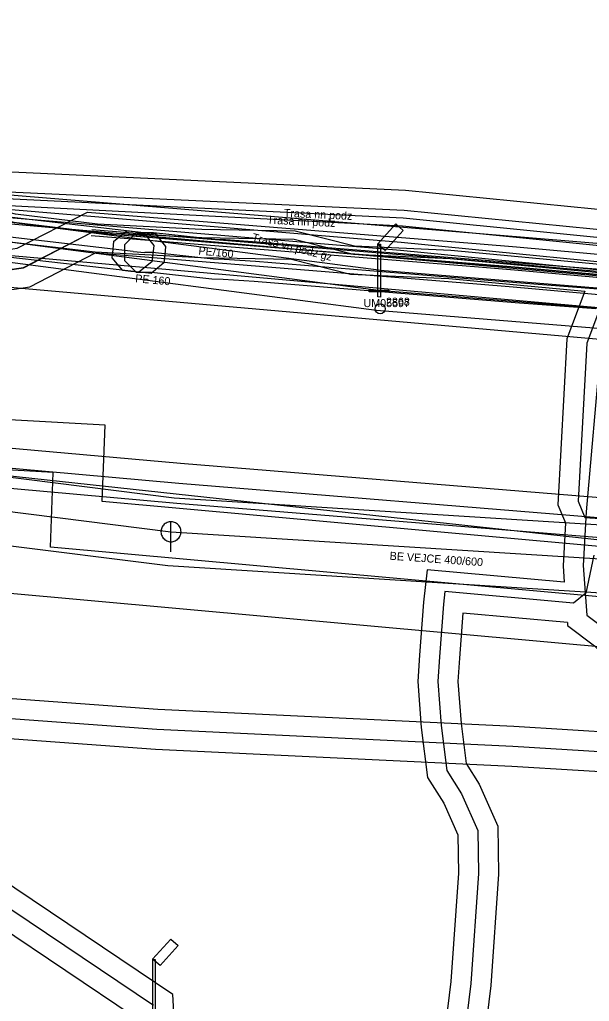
# Model space of a CAD drawing. Extents: x -762993 to -761845, y -975230 to -974501.
# Drawn here: x -762240.82 to -762212.37, y -975032.89 to -974983.83 of the extents above; entities that cross this region are included whole.
import ezdxf

# ---------------------------------------------------------------- set-up
doc = ezdxf.new("R2010")
doc.units = 0
for name, color, linetype in [('IS_CETIN_chranicka', 7, 'Continuous'), ('IS_CETIN_OP', 7, 'Continuous'), ('IS_CETIN_podzem optika zam', 7, 'Continuous'), ('IS_CETIN_podzem out of order', 7, 'Continuous'), ('IS_CEZ-D_anotace', 7, 'Continuous'), ('IS_CEZ-D_el vedeni NN podzem', 7, 'Continuous'), ('IS_CEZ-D_el vedeni VN podzem', 7, 'Continuous'), ('IS_CEZ-D_el vedeni VN podzem soubeh investice', 7, 'Continuous'), ('IS_CEZ-D_OP', 7, 'Continuous'), ('IS_CEZ-T_parovod', 7, 'Continuous'), ('IS_CEZ-T_parovod OP', 7, 'Continuous'), ('IS_CRA_podzem telekomunikace', 7, 'Continuous'), ('IS_DPmUL_OP', 7, 'Continuous'), ('IS_DPmUL_trakce anotace', 7, 'Continuous'), ('IS_DPmUL_trakce stozary', 7, 'Continuous'), ('IS_DPmUL_VO lampy', 7, 'Continuous'), ('IS_DPmUL_VO lampy anotace', 7, 'Continuous'), ('IS_DPmUL_VO vedeni podzem', 7, 'Continuous'), ('IS_GASNET_plyn NTL anotace', 7, 'Continuous'), ('IS_GASNET_plyn NTL rad', 7, 'Continuous'), ('IS_GASNET_plyn OP', 7, 'Continuous'), ('IS_SCVK_kanalizace anotace', 7, 'Continuous'), ('IS_SCVK_kanalizace jednotna', 7, 'Continuous'), ('IS_SCVK_kanalizace OP', 7, 'Continuous'), ('IS_SCVK_kanalizace znaky', 7, 'Continuous'), ('IS_SCVK_vodovod anotace', 7, 'Continuous'), ('IS_SCVK_vodovod OP', 7, 'Continuous'), ('IS_SCVK_vodovod privadec', 7, 'Continuous'), ('IS_TPS_podzem metalika', 7, 'Continuous')]:
    doc.layers.add(name, color=color, linetype=linetype)

msp = doc.modelspace()

# ---------------------------------------------------------------- linework, layer by layer
at = {"layer": 'IS_CETIN_chranicka'}
for points in [[(-762237.218, -974994.31), (-762217.891, -974995.882), (-762216.077, -974996.031), (-762184.637, -974998.851)], [(-762237.242, -974994.61), (-762217.915, -974996.182), (-762216.103, -974996.329), (-762184.663, -974999.149)]]:
    msp.add_lwpolyline(points, dxfattribs=at)
at = {"layer": 'IS_CETIN_OP'}
for points in [[(-762244.715, -974995.213), (-762242.485, -974995.472), (-762240.94, -974995.245), (-762237.434, -974993.44), (-762217.822, -974995.035)], [(-762217.822, -974995.035), (-762216.005, -974995.184), (-762184.57, -974998.003), (-762178.542, -974998.433), (-762152.471, -975000.654), (-762131.203, -975002.624), (-762124.809, -975003.153), (-762118.93, -975003.623), (-762113.193, -975004.083), (-762107.364, -975004.514), (-762100.398, -975005.204), (-762087.589, -975006.295)], [(-762244.386, -974997.264), (-762242.455, -974997.488), (-762240.32, -974997.175), (-762237.026, -974995.48), (-762217.984, -974997.029)], [(-762217.984, -974997.029), (-762216.175, -974997.176), (-762184.73, -974999.997), (-762178.698, -975000.427), (-762152.649, -975002.646), (-762131.377, -975004.616), (-762124.971, -975005.147), (-762119.09, -975005.617), (-762113.347, -975006.077), (-762107.536, -975006.506), (-762100.582, -975007.196), (-762087.759, -975008.287)], [(-762244.95, -975004.903), (-762232.795, -975005.994), (-762211.223, -975007.754), (-762199.605, -975008.834), (-762199.09, -975008.874)], [(-762246.119, -975006.806), (-762232.965, -975007.986), (-762211.397, -975009.746), (-762200.31, -975010.777)]]:
    msp.add_lwpolyline(points, dxfattribs=at)
at = {"layer": 'IS_CETIN_podzem optika zam'}
for points in [[(-762274.13, -974988.8), (-762260.53, -974993.46), (-762251.6, -974995.42), (-762242.47, -974996.48), (-762240.63, -974996.21), (-762237.23, -974994.46), (-762217.903, -974996.032)], [(-762217.903, -974996.032), (-762216.09, -974996.18), (-762184.65, -974999), (-762178.62, -974999.43), (-762152.56, -975001.65), (-762131.29, -975003.62), (-762124.89, -975004.15), (-762119.01, -975004.62), (-762113.27, -975005.08), (-762107.45, -975005.51), (-762100.49, -975006.2), (-762087.674, -975007.291)], [(-762246.03, -975005.81), (-762232.88, -975006.99), (-762211.31, -975008.75), (-762199.69, -975009.83), (-762199.18, -975009.87)]]:
    msp.add_lwpolyline(points, dxfattribs=at)
at = {"layer": 'IS_CETIN_podzem out of order'}
msp.add_lwpolyline([(-762250.2, -975005.66), (-762210.15, -975010), (-762201.16, -975010.99), (-762121.16, -975017.35), (-762071.23, -975020.85), (-762043.47, -975023.41)], dxfattribs=at)
at = {"layer": 'IS_CEZ-D_el vedeni NN podzem'}
for points in [[(-762193.524, -974995.955), (-762195.916, -974995.748), (-762195.968, -974996.181), (-762206.85, -974995.622), (-762221.698, -974994.154), (-762246.209, -974992.883), (-762248.603, -974989.634), (-762249.046, -974987.054), (-762248.934, -974986.091), (-762247.847, -974984.536), (-762246.114, -974982.893)], [(-762193.524, -974995.955), (-762196.315, -974995.713), (-762196.321, -974995.763), (-762206.82, -974995.223), (-762221.661, -974993.755), (-762245.947, -974992.564), (-762248.224, -974989.473), (-762248.642, -974987.043), (-762248.543, -974986.191), (-762247.498, -974984.757), (-762245.839, -974983.184), (-762245.485, -974982.848), (-762245.111, -974983.239), (-762244.564, -974983.81), (-762244.131, -974983.395)], [(-762193.524, -974995.955), (-762196.714, -974995.678), (-762196.674, -974995.344), (-762206.79, -974994.824), (-762221.625, -974993.357), (-762245.684, -974992.246), (-762247.846, -974989.312), (-762248.238, -974987.032), (-762248.152, -974986.29), (-762247.149, -974984.977), (-762245.644, -974983.55), (-762245.499, -974983.413), (-762245.127, -974983.801), (-762244.853, -974984.087), (-762244.131, -974983.395)], [(-762193.524, -974995.956), (-762193.614, -974996.71), (-762193.822, -974998.453), (-762211.362, -974996.973), (-762212.503, -974999.99), (-762212.93, -975007.897), (-762212.59, -975008.699), (-762208.023, -975009.002), (-762208.841, -975020.191), (-762208.871, -975020.599), (-762216.194, -975020.151), (-762233.978, -975019.299), (-762252.877, -975017.917), (-762257.832, -975017.547), (-762262.774, -975017.178), (-762264.709, -975017.162), (-762266.642, -975017.146), (-762269.935, -975017.363)], [(-762211.822, -975000.258), (-762212.529, -975008.421), (-762212.681, -975011.104), (-762212.495, -975013.581), (-762211.454, -975014.362)], [(-762212.14, -975010.58), (-762212.55, -975012.48), (-762213.16, -975012.98), (-762219.59, -975012.4), (-762219.66, -975013.03), (-762219.86, -975015.66), (-762219.94, -975016.9), (-762219.77, -975019.1), (-762219.49, -975021.35), (-762218.75, -975022.51), (-762217.94, -975024.34), (-762217.91, -975026.5), (-762218.29, -975031.99), (-762219.04, -975038.13)]]:
    msp.add_lwpolyline(points, dxfattribs=at)
at = {"layer": 'IS_CEZ-D_el vedeni VN podzem'}
for points in [[(-762269.579, -974969.967), (-762269.216, -974971.463), (-762268.263, -974975.531), (-762267.512, -974976.705), (-762264.757, -974978.053), (-762262.777, -974978.189), (-762259.951, -974977.791), (-762257.059, -974975.091), (-762254.069, -974975.768), (-762249.558, -974980.329), (-762249.105, -974980.676), (-762247.006, -974982.026), (-762245.904, -974982.859), (-762247.37, -974986.49), (-762247.43, -974987.01), (-762247.09, -974988.99), (-762245.16, -974991.61), (-762241.64, -974993.28), (-762221.77, -974994.95), (-762206.91, -974996.42), (-762195.262, -974997.018), (-762195.119, -974995.819), (-762194.458, -974994.436)], [(-762269.605, -974971.556), (-762268.637, -974975.689), (-762267.788, -974977.015), (-762264.863, -974978.447), (-762262.763, -974978.591), (-762259.77, -974978.169), (-762256.941, -974975.528), (-762254.271, -974976.132), (-762249.823, -974980.63), (-762249.335, -974981.004), (-762247.235, -974982.354), (-762246.39, -974982.993), (-762247.761, -974986.39), (-762247.834, -974987.021), (-762247.468, -974989.151), (-762245.422, -974991.928), (-762241.746, -974993.673), (-762221.806, -974995.348), (-762206.94, -974996.819), (-762194.909, -974997.437), (-762194.72, -974995.856), (-762194.458, -974994.436)], [(-762245.09, -974982.81), (-762246.99, -974984.79), (-762247.4, -974985.77), (-762247.54, -974987.01), (-762247.5, -974988.33), (-762246.71, -974990.37), (-762245.42, -974991.69), (-762241.81, -974993.76), (-762241.12, -974993.94), (-762236.96, -974994.44), (-762231.73, -974994.71), (-762227.11, -974994.8), (-762224.15, -974995.55), (-762219.32, -974995.76), (-762207.1, -974996.91), (-762200.67, -974997.34), (-762199.56, -974997.3), (-762198.56, -974996.73), (-762198.04, -974995.71)]]:
    msp.add_lwpolyline(points, dxfattribs=at)
at = {"layer": 'IS_CEZ-D_el vedeni VN podzem soubeh investice'}
msp.add_lwpolyline([(-762198.314, -974995.373), (-762198.862, -974996.442), (-762199.673, -974996.904), (-762200.675, -974996.938), (-762207.068, -974996.511), (-762219.294, -974995.361), (-762224.092, -974995.152), (-762227.056, -974994.401), (-762231.716, -974994.31), (-762236.926, -974994.041), (-762241.03, -974993.548), (-762241.657, -974993.386), (-762245.172, -974991.371), (-762246.367, -974990.149), (-762247.098, -974988.261), (-762247.139, -974987.026), (-762247.003, -974985.858), (-762246.655, -974985.018), (-762244.801, -974983.086)], dxfattribs=at)
at = {"layer": 'IS_CEZ-D_OP'}
for points in [[(-762193.437, -974994.959), (-762195.598, -974994.771), (-762195.554, -974994.4), (-762206.715, -974993.827), (-762221.553, -974992.359), (-762243.371, -974991.352)], [(-762243.344, -974994.033), (-762242.192, -974994.694), (-762241.307, -974994.925), (-762237.046, -974995.437), (-762231.766, -974995.709), (-762227.244, -974995.798), (-762224.296, -974996.545), (-762219.389, -974996.758), (-762212.592, -974997.398)], [(-762212.592, -974997.398), (-762213.493, -974999.781), (-762213.941, -975008.074), (-762213.562, -975008.969)], [(-762213.562, -975008.969), (-762213.683, -975011.113), (-762213.621, -975011.934)], [(-762213.621, -975011.934), (-762220.476, -975011.316), (-762220.656, -975012.937), (-762220.858, -975015.59), (-762220.942, -975016.906), (-762220.765, -975019.2), (-762220.454, -975021.698), (-762219.634, -975022.984), (-762218.937, -975024.558), (-762218.91, -975026.472), (-762219.286, -975031.895), (-762220.036, -975038.04)], [(-762210.784, -975019.48), (-762216.14, -975019.152), (-762233.918, -975018.301), (-762252.803, -975016.92), (-762257.758, -975016.55), (-762262.733, -975016.178), (-762264.701, -975016.162), (-762266.671, -975016.146), (-762270.081, -975016.37), (-762273.062, -975017.056), (-762274.852, -975017.621), (-762277.427, -975019.146), (-762279.613, -975021.175), (-762281.167, -975023.071), (-762282.764, -975025.331), (-762283.845, -975028.749), (-762293.788, -975024.216), (-762299.936, -975020.663), (-762307.64, -975012.706), (-762307.985, -975012.349)], [(-762209.615, -975021.555), (-762216.248, -975021.15), (-762234.038, -975020.297), (-762252.951, -975018.914), (-762257.906, -975018.544), (-762262.815, -975018.178), (-762264.717, -975018.162), (-762266.613, -975018.146), (-762269.789, -975018.356), (-762272.536, -975018.988), (-762274.03, -975019.459), (-762276.223, -975020.758), (-762278.153, -975022.549), (-762279.575, -975024.283), (-762280.95, -975026.231), (-762282.619, -975031.505), (-762294.706, -975025.996), (-762301.178, -975022.255), (-762309.078, -975014.096), (-762309.618, -975013.538), (-762311.559, -975013.102)], [(-762213.47, -975013.956), (-762218.692, -975013.485), (-762218.862, -975015.73), (-762218.938, -975016.894), (-762218.775, -975019), (-762218.526, -975021.002), (-762217.866, -975022.036), (-762216.943, -975024.122), (-762216.91, -975026.528), (-762217.294, -975032.085), (-762218.044, -975038.22)], [(-762213.47, -975013.956), (-762213.458, -975014.109), (-762212.114, -975015.117), (-762211.095, -975016.152), (-762210.675, -975016.963), (-762210.784, -975019.48)]]:
    msp.add_lwpolyline(points, dxfattribs=at)
at = {"layer": 'IS_CEZ-T_parovod'}
msp.add_lwpolyline([(-761997.94, -975128.34), (-762040.63, -975080.79), (-762092.91, -975023.16), (-762093.78, -975023), (-762095.1, -975022.88), (-762139.5, -975019.26), (-762139.25, -975015.36), (-762142, -975015.09), (-762142.45, -975019.26), (-762189.8, -975015.24), (-762189.54, -975011.07), (-762194.02, -975010.75), (-762194.39, -975014.25), (-762239.28, -975010.18), (-762239.14, -975006.45), (-762242.94, -975006.24), (-762243.22, -975009.53), (-762252.6, -975008.69), (-762274.12, -975007.08), (-762277.86, -975004.82)], dxfattribs=at)
at = {"layer": 'IS_CEZ-T_parovod OP'}
for points in [[(-761996.08, -975126.67), (-762038.774, -975079.115), (-762091.626, -975020.854), (-762093.44, -975020.521), (-762094.885, -975020.389), (-762136.848, -975016.968), (-762136.601, -975013.108), (-762144.22, -975012.36), (-762144.673, -975016.562), (-762187.153, -975012.956), (-762186.891, -975008.753), (-762196.252, -975008.084), (-762196.617, -975011.538), (-762236.693, -975007.904), (-762236.55, -975004.089), (-762245.225, -975003.61), (-762245.498, -975006.816), (-762252.395, -975006.198), (-762273.338, -975004.632), (-762275.663, -975003.227)], [(-761999.8, -975130.01), (-762042.486, -975082.465), (-762094.187, -975025.473), (-762095.315, -975025.371), (-762140.2, -975021.711), (-762140.227, -975021.958), (-762192.447, -975017.524), (-762192.411, -975016.94), (-762241.867, -975012.456), (-762241.856, -975012.162), (-762252.805, -975011.182), (-762274.902, -975009.528), (-762278.275, -975007.49)]]:
    msp.add_lwpolyline(points, dxfattribs=at)
at = {"layer": 'IS_CRA_podzem telekomunikace'}
msp.add_lwpolyline([(-762257.583, -974994.102), (-762251.601, -974995.42), (-762242.483, -974996.496), (-762240.634, -974996.224), (-762237.225, -974994.464), (-762216.085, -974996.188), (-762184.646, -974998.998), (-762178.626, -974999.438), (-762152.565, -975001.658), (-762131.295, -975003.618), (-762124.896, -975004.158), (-762119.016, -975004.628), (-762113.267, -975005.088), (-762107.455, -975005.508), (-762100.504, -975006.198), (-762086.855, -975007.364)], dxfattribs=at)
at = {"layer": 'IS_DPmUL_OP'}
for p, q in [((-762235.106, -975033.652), (-762260.567, -975016.515)), ((-762233.168, -975032.546), (-762256.457, -975016.87)), ((-762231.311, -975064.327), (-762233.168, -975032.546))]:
    msp.add_line(p, q, dxfattribs=at)
for points in [[(-762222.768, -974996.366), (-762241.607, -974993.905), (-762243.963, -974993.046)], [(-762223.004, -974998.353), (-762242.085, -974995.859), (-762244.155, -974995.105)], [(-762197.743, -974998.649), (-762211.975, -974997.251), (-762222.816, -974996.361)], [(-762197.933, -975000.64), (-762212.155, -974999.243), (-762223.004, -974998.353)]]:
    msp.add_lwpolyline(points, dxfattribs=at)
at = {"layer": 'IS_DPmUL_trakce stozary'}
msp.add_circle((-762222.818, -974998.273), 0.25, dxfattribs=at)
at = {"layer": 'IS_DPmUL_VO lampy'}
for points in [[(-762222.038, -974994.028), (-762221.668, -974994.358), (-762222.568, -974995.358), (-762222.948, -974995.038)], [(-762222.928, -974995.038), (-762222.808, -974995.048), (-762222.808, -974997.688), (-762222.928, -974997.678)], [(-762223.378, -974997.338), (-762222.378, -974997.338), (-762222.378, -974997.428), (-762223.368, -974997.428)], [(-762233.277, -975029.769), (-762232.907, -975030.099), (-762233.807, -975031.099), (-762234.187, -975030.779)], [(-762234.167, -975030.779), (-762234.047, -975030.789), (-762234.047, -975033.429), (-762234.167, -975033.419)]]:
    msp.add_lwpolyline(points, close=True, dxfattribs=at)
at = {"layer": 'IS_DPmUL_VO vedeni podzem'}
for points in [[(-762222.898, -974997.358), (-762241.846, -974994.882), (-762245.403, -974993.586), (-762246.542, -975005.345), (-762246.899, -975006.161), (-762256.821, -975004.998)], [(-762197.841, -974999.644), (-762212.065, -974998.247), (-762222.898, -974997.358)], [(-762234.137, -975033.099), (-762260.819, -975015.14)]]:
    msp.add_lwpolyline(points, dxfattribs=at)
at = {"layer": 'IS_GASNET_plyn NTL rad'}
for points in [[(-762235.16, -974995.41), (-762241.303, -974994.697), (-762241.895, -974994.628), (-762245.49, -974994.21), (-762251.83, -974984.63), (-762254.68, -974981.6), (-762255.58, -974980.65), (-762257.13, -974979.62), (-762258.52, -974978.68), (-762260.62, -974979.38), (-762261.995, -974979.661), (-762262.553, -974979.775), (-762262.92, -974979.85), (-762265.56, -974979.89), (-762268.53, -974977.47), (-762279.25, -974979.81)], [(-762235.16, -974995.41), (-762234.57, -974995.47)], [(-762152.06, -975002.65), (-762164.37, -975001.57), (-762171.49, -975000.8), (-762180.35, -975000.05), (-762191.928, -974999.15), (-762192.87, -974999.06), (-762193.62, -974998.98), (-762196.019, -974998.86), (-762209.34, -974997.53), (-762211.92, -974997.29), (-762211.926, -974997.289), (-762215.99, -974996.98), (-762229.04, -974995.92), (-762230.6, -974995.81), (-762231.15, -974995.79), (-762234.191, -974995.47), (-762234.57, -974995.47)]]:
    msp.add_lwpolyline(points, dxfattribs=at)
at = {"layer": 'IS_GASNET_plyn OP'}
for points in [[(-762253.953, -974980.914), (-762251.043, -974984.007), (-762244.913, -974993.27), (-762241.779, -974993.635), (-762241.187, -974993.704), (-762235.045, -974994.417), (-762234.633, -974994.465), (-762234.119, -974995.114), (-762234.167, -974995.525), (-762234.215, -974995.937), (-762234.864, -974996.451), (-762235.275, -974996.403), (-762241.419, -974995.69), (-762242.011, -974995.621), (-762245.605, -974995.203), (-762245.825, -974995.178), (-762246.202, -974994.947), (-762246.324, -974994.762), (-762252.617, -974985.253), (-762255.407, -974982.286)], [(-762212.049, -974998.282), (-762216.068, -974997.977), (-762229.116, -974996.917), (-762230.653, -974996.809), (-762231.221, -974996.788), (-762234.243, -974996.47), (-762234.57, -974996.47), (-762234.984, -974996.47), (-762235.57, -974995.884), (-762235.57, -974995.47), (-762235.57, -974995.056), (-762234.984, -974994.47), (-762234.57, -974994.47), (-762234.139, -974994.47), (-762231.079, -974994.792), (-762230.547, -974994.811), (-762228.964, -974994.923), (-762215.912, -974995.983), (-762211.806, -974996.295)]]:
    msp.add_lwpolyline(points, dxfattribs=at)
msp.add_lwpolyline([(-762235.471, -974994.373), (-762235.059, -974994.415), (-762234.469, -974994.475), (-762234.057, -974994.517), (-762233.533, -974995.159), (-762233.575, -974995.571), (-762233.617, -974995.983), (-762234.259, -974996.507), (-762234.671, -974996.465), (-762235.261, -974996.405), (-762235.673, -974996.363), (-762236.197, -974995.721), (-762236.155, -974995.309), (-762236.113, -974994.897)], close=True, dxfattribs=at)
at = {"layer": 'IS_SCVK_kanalizace jednotna'}
for points in [[(-762270.284, -975004.741), (-762233.263, -975009.418)], [(-762233.263, -975009.418), (-762195.393, -975011.808)]]:
    msp.add_lwpolyline(points, dxfattribs=at)
at = {"layer": 'IS_SCVK_kanalizace OP'}
for p, q in [((-762269.759, -975003.094), (-762233.103, -975007.725)), ((-762270.809, -975006.388), (-762233.423, -975011.111)), ((-762233.103, -975007.725), (-762195.236, -975010.115)), ((-762233.423, -975011.111), (-762195.55, -975013.501))]:
    msp.add_line(p, q, dxfattribs=at)
at = {"layer": 'IS_SCVK_kanalizace znaky'}
for points in [[(-762232.763, -975009.418), (-762232.765, -975009.364), (-762232.775, -975009.31), (-762232.79, -975009.257), (-762232.81, -975009.206), (-762232.836, -975009.158), (-762232.867, -975009.113), (-762232.903, -975009.071), (-762232.943, -975009.034), (-762232.986, -975009.001), (-762233.034, -975008.974), (-762233.084, -975008.951), (-762233.136, -975008.935), (-762233.189, -975008.924), (-762233.244, -975008.919), (-762233.299, -975008.92), (-762233.353, -975008.927), (-762233.407, -975008.939), (-762233.458, -975008.958), (-762233.507, -975008.982), (-762233.553, -975009.011), (-762233.596, -975009.046), (-762233.635, -975009.084), (-762233.669, -975009.127), (-762233.699, -975009.173), (-762233.723, -975009.222), (-762233.741, -975009.274), (-762233.754, -975009.327), (-762233.761, -975009.381), (-762233.763, -975009.436), (-762233.758, -975009.491), (-762233.747, -975009.544), (-762233.73, -975009.596), (-762233.708, -975009.646), (-762233.681, -975009.694), (-762233.648, -975009.738), (-762233.611, -975009.778), (-762233.569, -975009.814), (-762233.524, -975009.845), (-762233.476, -975009.871), (-762233.425, -975009.891), (-762233.373, -975009.906), (-762233.319, -975009.915), (-762233.264, -975009.918), (-762233.209, -975009.915), (-762233.155, -975009.906), (-762233.103, -975009.892), (-762233.052, -975009.871), (-762233.003, -975009.845), (-762232.958, -975009.814), (-762232.917, -975009.779), (-762232.879, -975009.739), (-762232.846, -975009.695), (-762232.819, -975009.648), (-762232.797, -975009.598), (-762232.78, -975009.546), (-762232.769, -975009.492), (-762232.764, -975009.437), (-762232.763, -975009.418)], [(-762233.263, -975010.418), (-762233.263, -975008.918)]]:
    msp.add_lwpolyline(points, dxfattribs=at)
at = {"layer": 'IS_SCVK_vodovod OP'}
for points in [[(-762257.658, -974992.58), (-762207.497, -974997.012), (-762202.898, -974997.152)], [(-762257.936, -974995.728), (-762207.685, -975000.168), (-762204.349, -975000.269)]]:
    msp.add_lwpolyline(points, dxfattribs=at)
at = {"layer": 'IS_SCVK_vodovod privadec'}
msp.add_lwpolyline([(-762257.797, -974994.154), (-762207.591, -974998.59), (-762203.041, -974998.728)], dxfattribs=at)
at = {"layer": 'IS_TPS_podzem metalika'}
msp.add_lwpolyline([(-762240.486, -974977.956), (-762246.238, -974984.004), (-762246.978, -974984.75), (-762247.396, -974985.793), (-762247.518, -974986.973), (-762247.497, -974988.28), (-762246.746, -974990.312), (-762245.354, -974991.693), (-762243.76, -974992.38), (-762227.7, -974993.7), (-762194.072, -974996.484), (-762193.869, -974994.354), (-762196.707, -974994.049), (-762196.809, -974992.782), (-762196.146, -974992.699), (-762192.513, -974992.502)], dxfattribs=at)

# ---------------------------------------------------------------- texts
at = {"layer": 'IS_CEZ-D_anotace'}
for s, rotation, p in [('Trasa nn podz', 357.3561, (-762227.632, -974993.68)), ('Trasa nn podz', 357.1924, (-762228.471, -974994.021)), ('Trasa vn podz gz', 345.7817, (-762229.247, -974994.878))]:
    msp.add_text(s, height=0.4, rotation=rotation, dxfattribs=at).set_placement(p)
at = {"layer": 'IS_DPmUL_trakce anotace'}
msp.add_text('2868', height=0.4, dxfattribs=at).set_placement((-762222.527, -974998.122))
at = {"layer": 'IS_DPmUL_VO lampy anotace'}
msp.add_text('UM05597', height=0.4, dxfattribs=at).set_placement((-762223.648, -974998.191))
at = {"layer": 'IS_GASNET_plyn NTL anotace'}
msp.add_text('PE/160', height=0.4, rotation=354.1933, dxfattribs=at).set_placement((-762231.906, -974995.559))
at = {"layer": 'IS_SCVK_kanalizace anotace'}
msp.add_text('BE VEJCE 400/600', height=0.4, rotation=356, dxfattribs=at).set_placement((-762222.354, -975010.813))
at = {"layer": 'IS_SCVK_vodovod anotace'}
msp.add_text('PE 160', height=0.4, rotation=355, dxfattribs=at).set_placement((-762235.06, -974996.951))

doc.saveas('drawing.dxf')
